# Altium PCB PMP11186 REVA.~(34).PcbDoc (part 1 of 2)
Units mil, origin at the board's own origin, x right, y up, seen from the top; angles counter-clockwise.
Board outline 5750 x 3370 mil, 4 copper layers (Top Layer, Signal Layer 1, Signal Layer 2, Bottom Layer), stack 85.4 mil thick; 92 components, 39 nets, 228 pads, 139 vias.
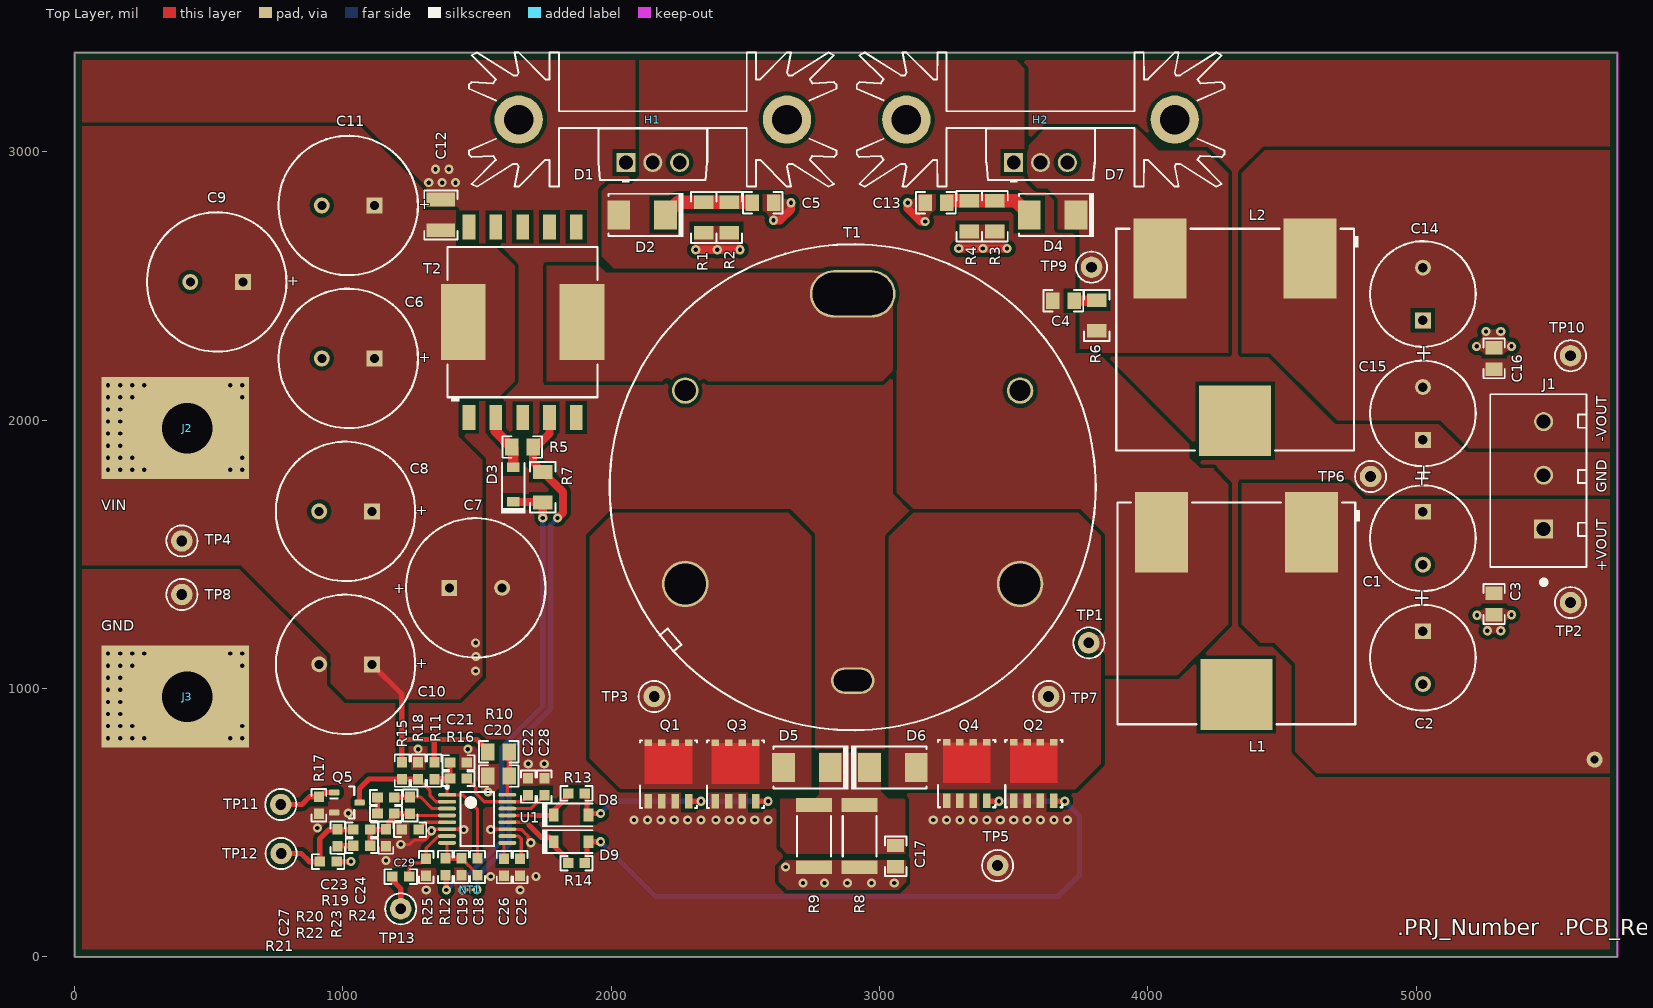
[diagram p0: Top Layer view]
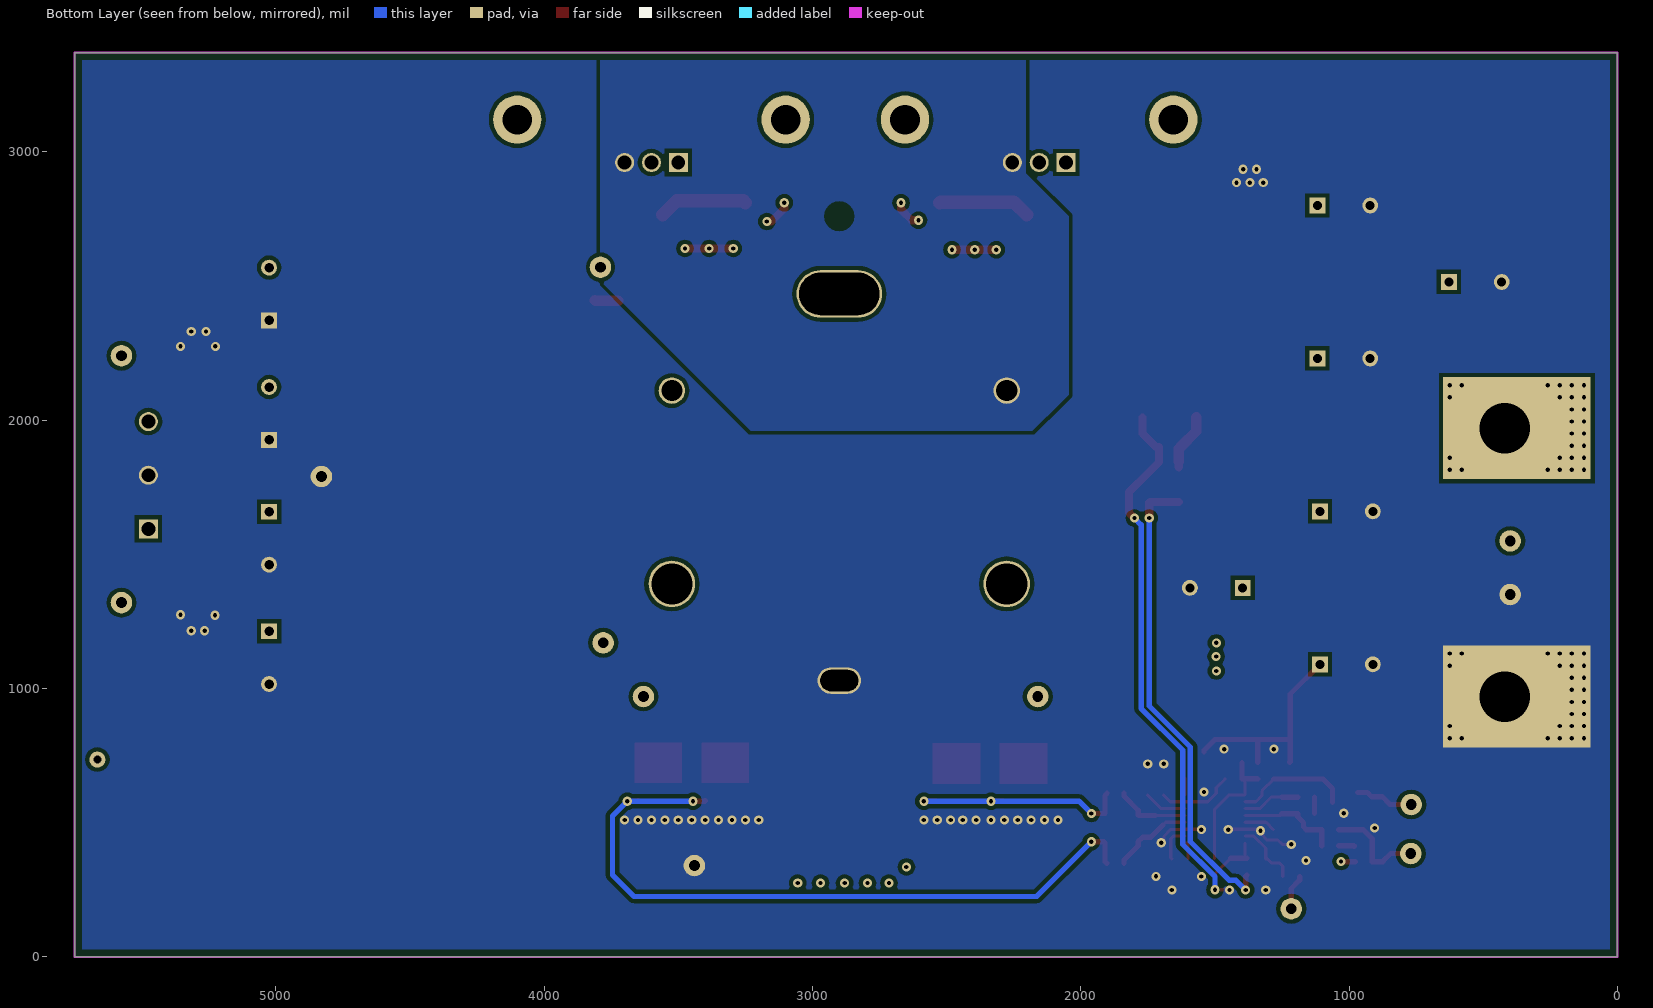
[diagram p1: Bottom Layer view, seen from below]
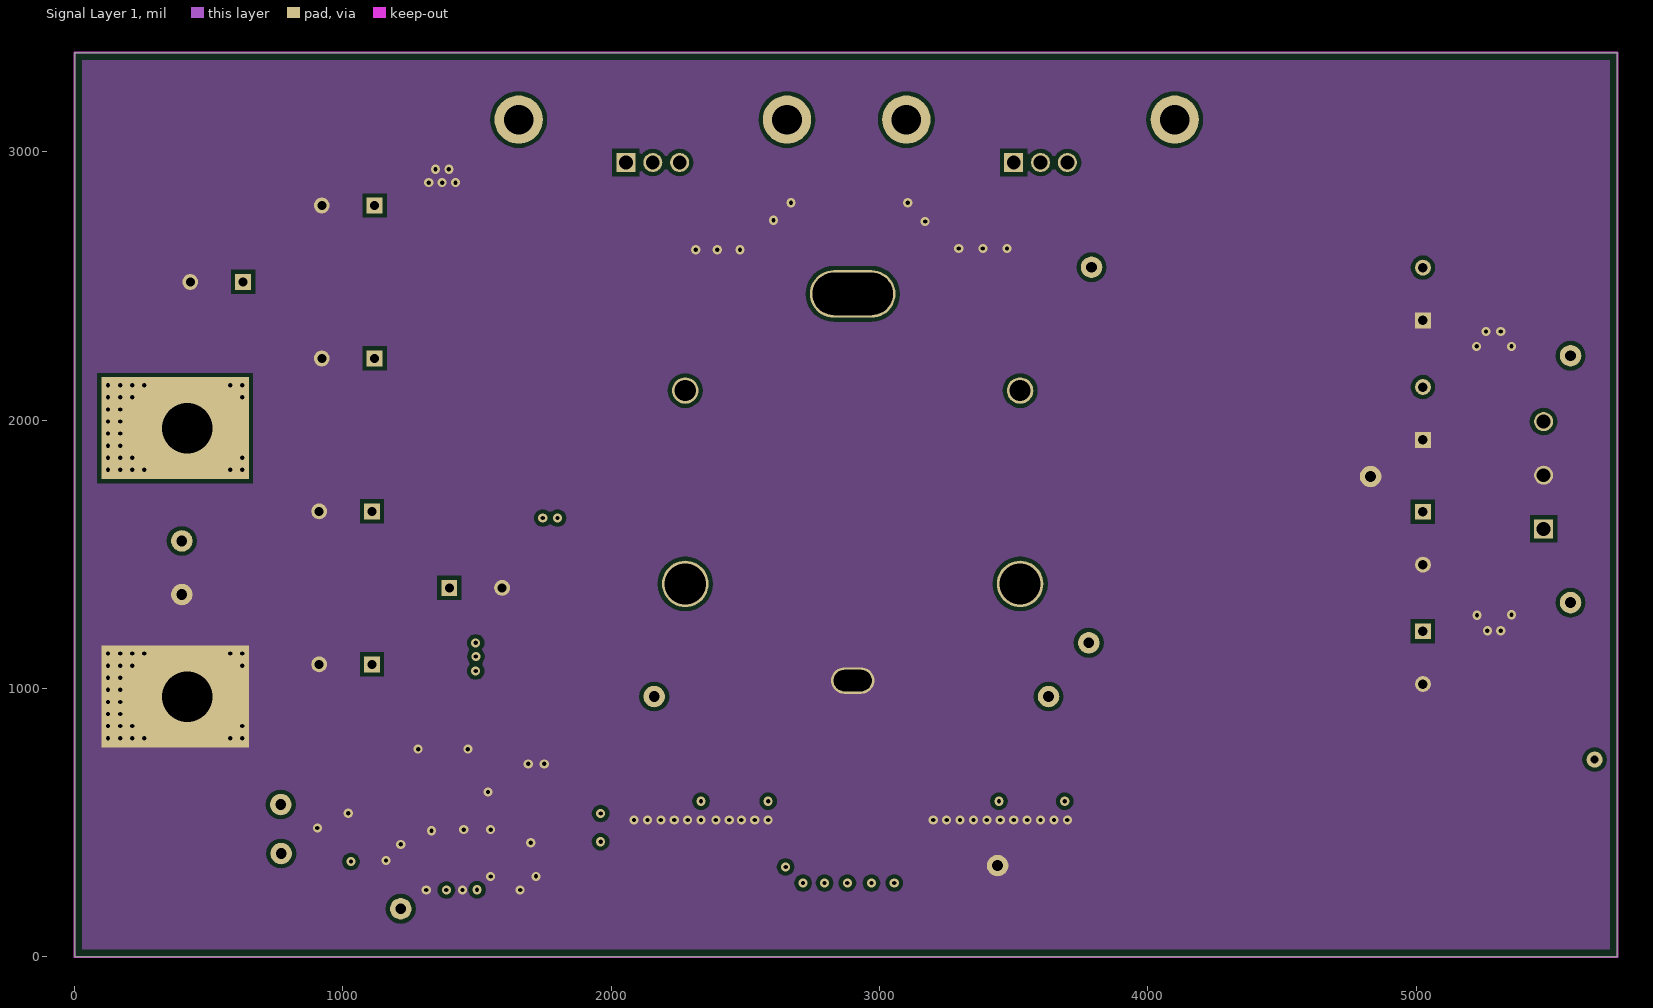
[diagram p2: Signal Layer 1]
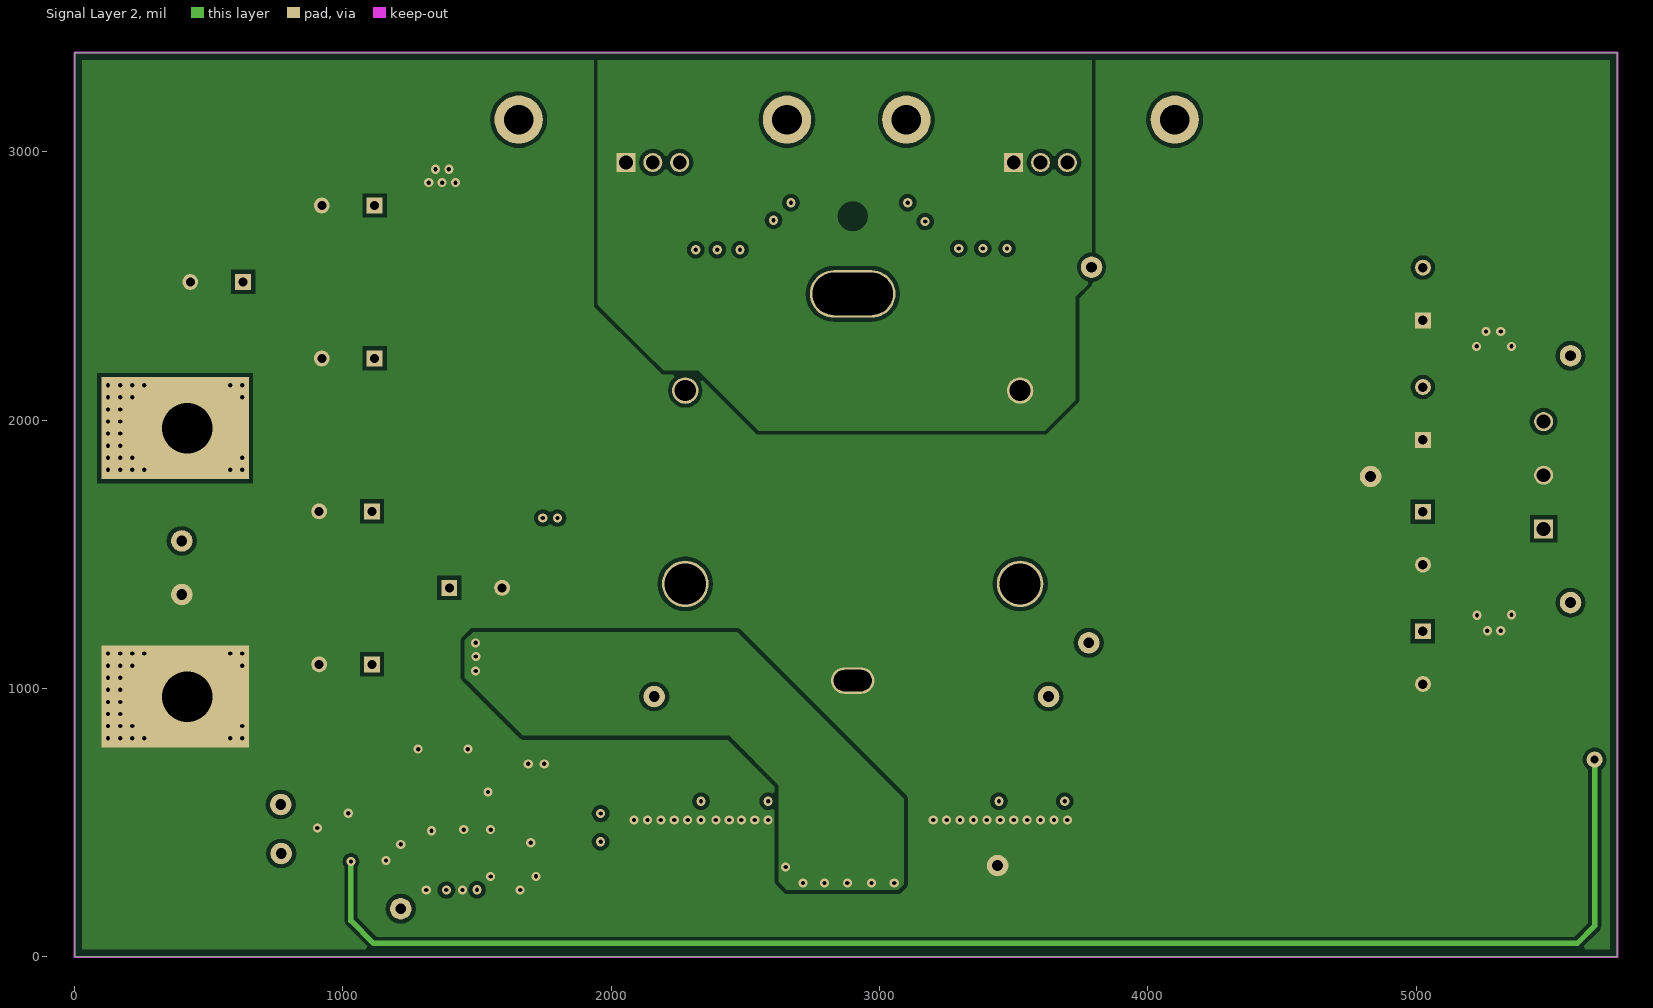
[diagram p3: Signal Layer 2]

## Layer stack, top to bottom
Top Solder: solder mask 0.4, Solder Resist, Dk 3.5
Top Layer: signal copper 2.8
Dielectric1: core 59.2, FR-4, Dk 4.8
Signal Layer 1: signal copper 2.8
Dielectric 3: prepreg 5, Dk 4.2
Signal Layer 2: signal copper 2.8
Dielectric 2: core 10, Dk 4.2
Bottom Layer: signal copper 2.8
Bottom Solder: solder mask 0.4, Solder Resist, Dk 3.5

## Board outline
0,0 5750,0 5750,3370 0,3370

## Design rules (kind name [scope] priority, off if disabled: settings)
AcuteAngle [All] p1: minimum=4.50000000000000E+0001 checktracksonly=FALSE
AssemblyTestPointUsage [All] p1: valid=2
Clearance Clearance_Keepouts [((IsTrack Or IsArc) And Not InPoly) And IsFree and IsKeepOut vs ((IsTrack Or IsArc) And Not InPoly) And IsFree and IsKeepOut] p1: gap=0
Clearance Clearance_BoardEdge_MountingHoles [OnCopper and InComponentClass('Mounting Holes') vs IsKeepOut] p2: gap=40
Clearance Clearance_BoardEdge_Poly [OnCopper and InPoly vs IsKeepOut] p3: gap=25
Clearance Clearance_BoardEdge [OnCopper and Not InComponentClass('Logo') and not InComponentClass('FiducialMark') and not InRegion(1000,500,4000,800) and Not IsKeepout vs IsKeepOut] p4: gap=25
Clearance Clearance_Poly [InPolygon] p5: gap=15
Clearance [All] p6: gap=7.87
ComponentClearance ComponentClearance_MountingHoles_FiducialMarks [InComponentClass('Mounting Holes') vs InComponentClass('FiducialMark')] p1: gap=50 collisioncheckmode=3 verticalgap=10 showdistances=FALSE
ComponentClearance ComponentClearance_Shunt [InComponentClass('Header') vs InComponentClass('Shunt')] p2: gap=0 collisioncheckmode=3 verticalgap=0 showdistances=FALSE
ComponentClearance ComponentClearance_Logo [InComponentClass('Logo')] p3: gap=50 collisioncheckmode=3 verticalgap=10 showdistances=FALSE
ComponentClearance ComponentClearance_ScrewToNut [(HasFootprint('NY PMS 440 0025 PH')) vs (HasFootprint('Keystone_1902C'))] p4: gap=5 collisioncheckmode=3 verticalgap=10 showdistances=FALSE
ComponentClearance ComponentClearance_MountingHoles [InComponentClass('Mounting Holes')] p5: gap=150 collisioncheckmode=3 verticalgap=100000 showdistances=FALSE
ComponentClearance ComponentClearance_SmallPassives [HasFootprint('0201*') or HasFootprint('0402*') or HasFootprint('0508') or HasFootprint('0603*') or HasFootprint('0612') or HasFootprint('0805*') or HasFootprint('0815*') or HasFootprint('0830*') or HasFootprint('1206*') or HasFootprint('1210*') or HasFootprint('1808*') or HasFootprint('1812*') or HasFootprint('1825*') or HasFootprint('2010*') or HasFootprint('2220*') or HasFootprint('2225*') or HasFootprint('2512*') or HasFootprint('2728*') or HasFootprint('3518*') vs HasFootprint('0201*') or HasFootprint('0402*') or HasFootprint('0508') or HasFootprint('0603*') or HasFootprint('0612') or HasFootprint('0805*') or HasFootprint('0815*') or HasFootprint('0830*') or HasFootprint('1206*') or HasFootprint('1210*') or HasFootprint('1808*') or HasFootprint('1812*') or HasFootprint('1825*') or HasFootprint('2010*') or HasFootprint('2220*') or HasFootprint('2225*') or HasFootprint('2512*') or HasFootprint('2728*') or HasFootprint('3518*')] p6: gap=15 collisioncheckmode=3 verticalgap=10 showdistances=FALSE
ComponentClearance ComponentClearance_THtoSMT [IsThruComponent vs IsSMTComponent] p7: gap=25 collisioncheckmode=3 verticalgap=30 showdistances=FALSE
ComponentClearance ComponentClearance_THtoTH [IsThruComponent vs IsThruComponent] p8: gap=25 collisioncheckmode=3 verticalgap=30 showdistances=FALSE
ComponentClearance [All] p9: gap=25 collisioncheckmode=3 verticalgap=10 showdistances=FALSE
DiffPairsRouting [All] p1: maxlimit=100 minlimit=10 mostfreqgap=10 toplayer_minwidth=15 toplayer_maxwidth=15 toplayer_prefwidth=15 midlayer1_minwidth=15 midlayer1_maxwidth=15 midlayer1_prefwidth=15 midlayer2_minwidth=15 midlayer2_maxwidth=15 midlayer2_prefwidth=15 bottomlayer_minwidth=15 bottomlayer_maxwidth=15 bottomlayer_prefwidth=15 maxuncoupledlength=1000
FabricationTestPointUsage TestPointUsage [All] p1: valid=2 allowmultiple=FALSE
FabricationTestpoint Testpoint [All] p1: side=3 testpointundercomponent=TRUE minsize=40 maxsize=100 preferedsize=60 minholesize=0 maxholesize=40 preferedholesize=32 testpointgrid=1 allowsidetop=TRUE allowsidebottom=TRUE usegrid=TRUE gridtolerance=0.01
FanoutControl Fanout_LCC [IsLCC] p1: bgadir=Out bgaviamode=Centered fanoutstyle=Auto fanoutdirection=Alternating viagrid=1 // Fanout_LCC (Default Rule)
FanoutControl Fanout_BGA [IsBGA] p2: bgadir=Out bgaviamode=Centered fanoutstyle=Auto fanoutdirection=Alternating viagrid=1 // Fanout_BGA (Default Rule)
FanoutControl Fanout_Default [All] p4: bgadir=Out bgaviamode=Centered fanoutstyle=Auto fanoutdirection=Alternating viagrid=1 // Fanout_Default (Default Rule)
FanoutControl Fanout_Small [(CompPinCount < 5)] p5: bgadir=Out bgaviamode=Centered fanoutstyle=Auto fanoutdirection=OutThenIn viagrid=1 // Fanout_Small (Default Rule)
HoleSize [All] p1: absolutevalues=TRUE maxlimit=251 minlimit=8 maxpercent=80.000 minpercent=20.000
MinimumAnnularRing MinimumAnnularRing_ThermalPadVias [IsVia and InAnyComponent] p1: minimumring=5.91
MinimumAnnularRing [All] p2: minimumring=9
MinimumSolderMaskSliver MinimumSolderMaskSliver_Logo [InComponentClass('Logo') vs InComponentClass('Logo')] p1: minsoldermaskwidth=0.7
MinimumSolderMaskSliver [All] p2: minsoldermaskwidth=3.94
PlaneClearance [All] p1: clearance=12
PlaneConnect [All] p1: planeconnectstyle=Direct reliefexpansion=10 reliefentries=4 reliefconductorwidth=10 reliefairgap=10
PolygonConnect [All] p1: connectstyle=Direct reliefconductorwidth=10 reliefentries=4 polygonreliefangle="90 Angle" airgapwidth=10
RoutingVias ThermalPadVias [IsVia and InAnyComponent] p1: holewidth=7.87 width=19.68 viastyle="Through Hole" minholewidth=7.87 minwidth=19.68 maxholewidth=12.99 maxwidth=23.62
RoutingVias [All] p2: holewidth=16 width=34 viastyle="Through Hole" minholewidth=7.87 minwidth=26 maxholewidth=40 maxwidth=65
SilkToBoardRegionClearance [Not ((IsComment or IsDesignator) And (Hide <> 'False')) and not InRegion(1000,500,4000,800)] p1:
SilkToSilkClearance SilkToSilkClearance_Pb-FreeLogo [(HasFootprint('Pb-Free_Overlay_Medium') OR HasFootprint('Pb-Free_Overlay_Small')) vs (HasFootprint('Pb-Free_Overlay_Medium') OR HasFootprint('Pb-Free_Overlay_Small'))] p1: silktosilkclearance=0
SilkToSilkClearance [All] p2: silktosilkclearance=0
SilkToSolderMaskClearance "Silk to Solder Mask Opening" [All] p1: minsilkscreentomaskgap=1 clearancetoexposedcopper=FALSE
SolderMaskExpansion [All] p1: expansion=1.97
UnpouredPolygon [All] p1: allowunpoured=FALSE
Width [All] p1: maxlimit=100 minlimit=6 preferedwidth=10 checkconnectedcopper=TRUE
13 further rules are at their usual default settings.

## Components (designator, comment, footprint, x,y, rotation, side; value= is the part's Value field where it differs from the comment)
C1 "35ZL470MEFC10X20" CAPPR5-10X20 5025,1560 r270 top
C2 "35ZL470MEFC10X20" CAPPR5-10X20 5025,1115 r270 top
C3 "GRM21BR71H105KA12L" 0805_HV 5290,1315 r270 top
C4 "GRM21A5C2E101JW01D" 0805_HV 3685,2445 r0 top
C5 "C2012X7R2A103M" 0805_HV 2565,2810 r0 top
C6 "25ZLH2700M12.5X35" ZLH_1250x2500 1020,2230 r180 top
C7 "25ZLH2700M12.5X35" ZLH_1250x2500 1495,1375 r0 top
C8 "25ZLH2700M12.5X35" ZLH_1250x2500 1010,1660 r180 top
C9 "25ZLH2700M12.5X35" ZLH_1250x2500 530,2515 r180 top
C10 "25ZLH2700M12.5X35" ZLH_1250x2500 1010,1090 r180 top
C11 "25ZLH2700M12.5X35" ZLH_1250x2500 1020,2800 r180 top
C12 "C3225X7R1E106M" 1210 1365,2765 r90 top
C13 "C2012X7R2A103M" 0805_HV 3210,2810 r0 top
C14 "35ZL470MEFC10X20" CAPPR5-10X20 5025,2470 r90 top
C15 "35ZL470MEFC10X20" CAPPR5-10X20 5025,2025 r90 top
C16 "GRM21BR71H105KA12L" 0805_HV 5290,2230 r270 top
C17 "C2012X7R2A103M" 0805_HV 3060,375 r90 top
C18 "C1608C0G1H152J" 0603 1501.98,335.31 r270 top
C19 "C1608C0G1H101J" 0603 1441.98,335.31 r90 top
C20 "C2012X7R1E105K" 0805_HV 1580.68,674.01 r180 top
C21 "" 0603 1430.68,724.01 r180 top
C22 "C1608X7R1C105K" 0603 1690.68,634.01 r270 top
C23 "C1608X7R1H473K" 0603 1160.68,594.01 r0 top
C24 "C1608C0G1H150J" 0603 1250.68,564.01 r270 top
C25 "C1608X7R1C105K" 0603 1660.68,334.01 r270 top
C26 "C1608X7R1H103K" 0603 1600.68,334.01 r270 top
C27 "" 0603 980.68,444.01 r90 top
C28 "C1608X7R1C105K" 0603 1750.68,634.01 r90 top
C29 "C1608C0G1H101J" 0603 1215.68,299.01 r0 top
D1 "FML22S" ITO-220AB 2155,2960 r0 top
D2 "MURS120-13-F" SMB 2115,2765 r180 top
D3 "MMSD4148T1G" SOD-123 1635,1760 r90 top
D4 "MURS120-13-F" SMB 3645,2765 r180 top
D5 "MURS120-13-F" SMB 2729.45,705.28 r180 top
D6 "MURS120-13-F" SMB 3049.45,705.28 r0 top
D7 "FML22R" ITO-220AB 3600,2960 r0 top
D8 "BAT54T1G" SOD-123 1850.68,529.01 r0 top
D9 "BAT54T1G" SOD-123 1850.68,429.01 r0 top
H1 "513201B02500G" HSINK_513201B02500 2155,3120 r0 top
H2 "513201B02500G" HSINK_513201B02500 3600,3120 r0 top
J1 "OSTTA034163" On-Shore_OSTTA034163 5455,1775 r90 top
J2 "CB35-36-CY" CB35-36-CY 420,1970 r0 top
J3 "CB35-36-CY" CB35-36-CY 420,970 r0 top
L1 "B82559A0353A020" B82559_1420 4330,1280 r270 top
L2 "B82559A0353A020" B82559_1420 4325,2300 r270 top
NT1 "Net-Tie" Net-Tie_10mil 1475,250 r180 top net-tie
Q1 "DNP" TRANS_NexFET_Q5B 2213.12,688.44 r90 top
Q2 "DNP" TRANS_NexFET_Q5B 3574.72,690.58 r90 top
Q3 "CSD18540Q5B" TRANS_NexFET_Q5B 2463.12,688.44 r90 top
Q4 "CSD18540Q5B" TRANS_NexFET_Q5B 3324.72,690.58 r90 top
Q5 "2N7002P,215" SOT-23 1015,575 r0 top
R1 "" 1206 2345,2755 r90 top
R2 "CRCW120649K9FKEA" 1206 2440,2755 r90 top
R3 "" 1206 3430,2760 r270 top
R4 "CRCW120649K9FKEA" 1206 3335,2760 r270 top
R5 "CRCW08051K00FKEA" 0805_HV 1668.74,1900 r0 top
R6 "CRCW1206100RFKEA" 1206 3810,2390 r90 top
R7 "CSR1206FKR750" 1206 1745,1750 r270 top
R8 "" 2512 2925.68,449.81 r270 top
R9 "CRCW251210K0JNEG" 2512 2755.68,449.81 r270 top
R10 "ERJ-6GEYJ4R7V" 0805_HV 1580.68,764.01 r180 top
R11 "" 0603 1340.68,694.01 r270 top
R12 "CRCW06031K00FKEA" 0603 1381.98,335.31 r270 top
R13 "CRCW06031R00FKEA" 0603 1870.68,609.01 r0 top
R14 "CRCW06031R00FKEA" 0603 1870.68,349.01 r0 top
R15 "CRCW0603130KFKEA" 0603 1220.68,694.01 r90 top
R16 "CRCW0603200KFKEA" 0603 1430.68,664.01 r180 top
R17 "CRCW060310K0FKEA" 0603 910.89,565 r90 top
R18 "CRCW060321K0FKEA" 0603 1280.68,694.01 r270 top
R19 "CRCW0603100KFKEA" 0603 1160.68,534.01 r180 top
R20 "CRCW060347K5FKEA" 0603 1070.68,474.01 r180 top
R21 "CRCW060349R9FKEA" 0603 945,355 r180 top
R22 "" 0603 1070.68,414.01 r180 top
R23 "CRCW06032K49FKEA" 0603 1160.68,444.01 r90 top
R24 "CRCW060349K9FKEA" 0603 1250.68,474.01 r0 top
R25 "CRCW060329K4FKEA" 0603 1310.68,334.01 r90 top
T1 "G154027ALF" GCI_G154027ALF 2900,1750 r90 top
T2 "G154028ALF" GCI_G154028ALF 1670,2365 r90 top
TP1 "5000" Keystone5000 3780,1170 r0 top
TP2 "5000" Keystone5000 5575,1320 r0 top
TP3 "5000" Keystone5000 2160,970 r0 top
TP4 "5000" Keystone5000 400,1550 r0 top
TP5 "5001" Keystone5001 3440,340 r0 top
TP6 "5001" Keystone5001 4830,1790 r0 top
TP7 "5000" Keystone5000 3630,970 r0 top
TP8 "5001" Keystone5001 400,1350 r0 top
TP9 "5000" Keystone5000 3790,2570 r0 top
TP10 "5000" Keystone5000 5575,2240 r0 top
TP11 "5000" Keystone5000 768.65,567.6 r0 top
TP12 "5000" Keystone5000 770,385 r0 top
TP13 "5000" Keystone5000 1215.68,179.01 r0 top
U1 "LM25037QMT" MTC16_N 1500.68,514.01 r0 top

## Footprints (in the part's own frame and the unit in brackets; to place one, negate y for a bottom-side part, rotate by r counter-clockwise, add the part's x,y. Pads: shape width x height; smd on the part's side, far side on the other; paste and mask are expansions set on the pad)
0603 [mm] "0603 from SM-752 data"
  rect 1x0.95 smd: 1(-0.8,0) 2(0.8,0)
  silkscreen extent -1.52,-0.69 1.52,0.69, body extent -0.87,-0.47 0.87,0.47, height 0.85
0805_HV [mil] "0805 with 30mil clearance between pads"
  rect 50x63 smd: 1(-40,0) 2(40,0)
  silkscreen extent -74,-40 74,40, body extent -43,-29 43,29, height 57
1206 [mm] "1206 from SM-752 data"
  rect 1.3x1.85 smd: 1(-1.45,0) 2(1.45,0)
  silkscreen extent -2.4,-1.21 2.4,1.21, body extent -1.7,-0.9 1.7,0.9, height 1.35
1210 [mm] "1210 from SM-752 data"
  rect 1.3x2.7 smd: 1(-1.45,0) 2(1.45,0)
  silkscreen extent -2.32,-1.57 2.32,1.57, body extent -1.7,-1.35 1.7,1.35, height 1.35
2512 [mm] "Chip Resistor, Body 6.3x3.2mm, IPC Medium Density"
  rect 1.3x3.4 smd: 1(-2.95,0) 2(2.95,0)
  silkscreen extent -1.9,-1.6 1.9,1.6, body extent -3.22,-1.67 3.22,1.67, height 0.71
B82559_1420 [mm] "SMD, 3-Leads, Body 21.5x21mm"
  rect 7.6x5 smd: 1(-7.675,7.1) 2(-7.675,-7.1)
  rect 6.7x6.8 smd: 3(7.675,0)
  silkscreen extent -10.5,-11.25 10.5,11.7, body extent -11,-11.25 11,11.25, height 14.2
CAPPR5-10X20 [mm] "Capacitor, Electrolytic, Radial; Body 10 x 20 mm (Dia.xH typ); Pin Spacing 5 mm (typ)"
  rect 1.5x1.5 hole 0.9: 1(-2.5,0)
  round 1.5 hole 0.9: 2(2.5,0)
  silkscreen extent -5,-5 5,5, body extent -5.01,-5.01 5.01,5.01, height 22
CB35-36-CY [mil] "Terminal 50A Lug"
  rect 550x380 hole 188 copper offset -45,0 paste-190: 1(0,0)
  body extent -960,-189 230,191, height 614
GCI_G154027ALF [mm] "TH, 6-Leads, Dia 46mm"
  round 4.4 hole 3.9: 1(-9.15,15.848) 3(-9.15,-15.848)
  oval 2.5x4.1 hole 2 slot 3.6 at 90 deg: 2(-18.3,0)
  round 2.5 hole 2: 4(9.15,-15.848) 6(9.15,15.848)
  oval 4.5x8.1 hole 4 slot 7.6 at 90 deg: 5(18.3,0)
  silkscreen extent -23,-23 23,23, body extent -23.01,-23.01 23.01,23.01, height 28
GCI_G154028ALF [mm] "SMD, 12-Leads, Body 14.2x20mm, Pitch 2.54mm"
  rect 2.35x1.2 smd: 1(-9.025,5.08) 2(-9.025,2.54) 3(-9.025,0) 4(-9.025,-2.54) 5(-9.025,-5.08) 6(9.025,-5.08) 7(9.025,-2.54) 8(9.025,0) 9(9.025,2.54) 10(9.025,5.08)
  rect 7.2x4.25 smd: 11(0,5.625) 12(0,-5.625)
  silkscreen extent -7.5,-7.1 7.1,7.1, body extent -10,-7.25 10,7.25, height 10.52
HSINK_513201B02500 [mil] "Aavid"
  round 180 hole 110.24: 1(-500,0) 2(500,0)
  silkscreen extent -685,-250 685,250, body extent -685,-250 685,250, height 2000
ITO-220AB [mm] "TH, 3-Leads, Body 10.11x15.87mm, Pitch 2.54mm"
  rect 1.8x1.8 hole 1.3: 1(-2.54,0)
  round 1.8 hole 1.3: 2(0,0) 3(2.54,0)
  silkscreen extent -5.16,-1.9 5.15,3.24, body extent -5.16,-1.66 5.16,3.24, height 19.67
Keystone5000 [mil] "For Keystone 500x miniature loop terminals"
  round 80 hole 40: 1(0,0)
  silkscreen extent -58,-58 58,58, body extent -49,-49 49,49, height 182
Keystone5001 [mil] "For Keystone 500x miniature loop terminals"
  round 80 hole 40: 1(0,0)
  silkscreen extent -58,-58 58,58, body extent -49,-49 49,49, height 182
MTC16_N [mm] "TSOP, 16-Leads, Body 5x4.4mm, Pitch 0.65mm, IPC Medium Density"
  oval 1.7x0.35 smd: 1(-2.85,2.275) 2(-2.85,1.625) 3(-2.85,0.975) 4(-2.85,0.325) 5(-2.85,-0.325) 6(-2.85,-0.975) 7(-2.85,-1.625) 8(-2.85,-2.275) 9(2.85,-2.275) 10(2.85,-1.625) 11(2.85,-0.975) 12(2.85,-0.325) 13(2.85,0.325) 14(2.85,0.975) 15(2.85,1.625) 16(2.85,2.275)
  silkscreen extent -2.97,-2.55 1.6,3.12, body extent -2.25,-2.55 2.25,2.55, height 1.1
Net-Tie_10mil [mil] "10mil net tie, no solder mask opening, no solder paste"
  rect 10x10 smd paste-5 mask-5: 1(-10,0) 2(10,0)
  Top Layer region: -6,5 6,5 6,-5 -6,-5
On-Shore_OSTTA034163 [mm] "TERM BLOCK 3x1, 5.08mm, TH"
  rect 1.8x1.8 hole 1.3: 1(-4.58,-0.5)
  round 1.8 hole 1.3 paste+0: 2(0.5,-0.5) 3(5.58,-0.5)
  silkscreen extent -9.73,-4.55 8.17,4.55, body extent -8.22,-4.6 8.22,4.6, height 13
SMB [mil] "Molded Diode, 2-Leads, Body 5.4x3.6mm, IPC Medium Density, based on OnSemi component dimensions"
  rect 85x107.99 smd: 1(-87.01,0) 2(87.01,0)
  silkscreen extent -155,-82 125,82, body extent -106,-71 106,71, height 91
SOD-123 [mm] "On Semi recommended land pattern"
  rect 0.915x1.22 smd: 1(-1.637,0) 2(1.637,0)
  silkscreen extent -2.74,-1.17 2.03,1.17, body extent -1.93,-0.9 1.93,0.9, height 1.35
SOT-23 [mm] "SOT23, 3-Leads, Body 2.9x1.3mm, Pitch 0.95mm, Lead Span 2.5mm, IPC Medium Density"
  rrect50% 1x0.6 smd: 1(-1.2,0.95) 2(-1.2,-0.95) 3(1.2,0)
  silkscreen extent -1.63,-1.5 0.7,1.5, body extent -1.16,-1.45 1.21,1.45, height 1
TRANS_NexFET_Q5B [mm] "TI recommended land pattern (nominal) November 2012"
  rect 1.372x0.71 smd paste-0.4: 1(-2.776,1.905) 2(-2.776,0.635) 3(-2.776,-0.635) 4(-2.776,-1.905)
  rect 0.59x0.71 smd paste-0.3: 5(2.776,-1.905) 6(2.776,-0.635) 7(2.776,0.635) 8(2.776,1.905)
  Top Layer region: -1.106,-2.26 2.744,-2.26 2.744,2.26 -1.106,2.26
  silkscreen extent -3.38,-2.7 3,2.7, body extent -3.23,-2.55 2.87,2.55, height 1.06
ZLH_1250x2500 [mm] "Rubycon"
  rect 1.5x1.5 hole 0.85: 1(-2.5,0)
  round 1.5 hole 0.85: 2(2.5,0)
  silkscreen extent -6.6,-6.6 6.6,6.6, body extent -6.45,-6.49 6.49,6.49, height 26.51

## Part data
C1 C2 C14 C15: "CAP, AL, 470 µF, 35 V, 0.023 Ohms, 1.82A, TH"
C3 C16: "CAP, CERM, 1uF, 50V, +/-10%, X7R, 0805"
C4: "CAP, CERM, 100 pF, 250 V, +/- 5%, C0G/NP0, 0805"
C5 C13 C17: "CAP, CERM, 0.01 µF, 100 V, +/- 20%, X7R, 0805"
C6 C7 C8 C9 C10 C11: library part 63ZLH470M12.5X25, "CAP, AL, 2700 µF, 25 V, 0.016 ohm, 4.12A, TH"
C12: "CAP, CERM, 10 µF, 25 V, +/- 20%, X7R, 1210"
C18: "CAP, CERM, 1500 pF, 50 V, +/- 5%, C0G/NP0, 0603"
C19 C29: "CAP, CERM, 100 pF, 50 V, +/- 5%, C0G/NP0, 0603"
C20: "CAP, CERM, 1 µF, 25 V, +/- 10%, X7R, 0805"
C21 C27: library part C1608C0G1H271J, "CAP, DNP, 0603"
C22 C25 C28: "CAP, CERM, 1 µF, 16 V, +/- 10%, X7R, 0603"
C23: "CAP, CERM, 0.047 µF, 50 V, +/- 10%, X7R, 0603"
C24: "CAP, CERM, 15 pF, 50 V, +/- 5%, C0G/NP0, 0603"
C26: "CAP, CERM, 0.01 µF, 50 V, +/- 10%, X7R, 0603"
D1 D7: "Diode, Ultrafast, 200 V, 10 A, TH"
D2 D4 D5 D6: "Diode, Superfast Rectifier, 200 V, 1 A, SMB"
D3: "Diode, Switching, 100 V, 0.2 A, SOD-123"
D8 D9: "Diode, Schottky, 30V, 0.2A, SOD-123"
H1 H2: "HEATSINK TO-218/TO-247 W/PINS 2\""
J1: "Terminal Block, 3x1, 5.08 mm, TH"
J2 J3: "Terminal 50A Lug"
L1 L2: "Inductor, Wirewound, Ferrite, 35 µH, 9.3 A, 0.007 ohm, SMD"
NT1: "Single point connection between nets."
Q1 Q2: library part CSD18540Q5B, "MOSFET, DNP, SON 5x6mm"
Q3 Q4: "MOSFET, N-CH, 60 V, 28 A, SON 5x6mm"
Q5: "MOSFET, N-CH, 60 V, 0.36 A, SOT-23"
R1 R3: library part CRCW120649K9FKEA, "RES, DNP, 1206"
R2 R4: "RES, 49.9 k, 1%, 0.25 W, 1206"
R5: "RES, 1.00 k, 1%, 0.125 W, 0805"
R6: "RES, 100 ohm, 1%, 0.25W, 1206"
R7: "RES, 0.75, 1%, 0.5 W, 1206"
R8: library part CRCW251210K0JNEG, "RES, DNP, 2512"
R9: "RES, 10 k, 5%, 1 W, 2512"
R10: "RES, 4.7, 5%, 0.125 W, 0805"
R11 R22: library part CRCW060332K4FKEA, "RES, DNP, 0603"
R12: "RES, 1.00 k, 1%, 0.1 W, 0603"
R13 R14: "RES, 1.00 ohm, 1%, 0.1W, 0603"
R15: "RES, 130 k, 1%, 0.1 W, 0603"
R16: "RES, 200 k, 1%, 0.1 W, 0603"
R17: "RES, 10.0k ohm, 1%, 0.1W, 0603"
R18: "RES, 21.0 k, 1%, 0.1 W, 0603"
R19: "RES, 100 k, 1%, 0.1 W, 0603"
R20: "RES, 47.5 k, 1%, 0.1 W, 0603"
R21: "RES, 49.9, 1%, 0.1 W, 0603"
R23: "RES, 2.49k ohm, 1%, 0.1W, 0603"
R24: "RES, 49.9 k, 1%, 0.1 W, 0603"
R25: "RES, 29.4 k, 1%, 0.1 W, 0603"
T1: "Transformer, 50 uH, TH"
T2: "Transformer, 22.4 mH, SMT"
TP1 TP2 TP3 TP4 TP7 TP9 TP10 TP11 TP12 TP13: "Test Point, Miniature, Red, TH"
TP5 TP6 TP8: "Test Point, Miniature, Black, TH"
U1: "Dual-Mode PWM Controller With Alternating Outputs, Automotive Grade, 16-pin TSSOP"

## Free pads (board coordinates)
  round 60 hole 30: 0(5665,735)

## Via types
v1: diameter 34, hole 16, Top Layer to Bottom Layer, 83 vias
v2: diameter 32, hole 16, Top Layer to Bottom Layer, 56 vias

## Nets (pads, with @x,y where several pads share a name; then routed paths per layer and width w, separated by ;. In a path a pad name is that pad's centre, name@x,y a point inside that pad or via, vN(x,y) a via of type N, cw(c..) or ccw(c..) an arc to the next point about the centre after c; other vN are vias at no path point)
GND: C1.2 C2.2 C3.2 C5.2 C6.2 C7.2 C8.2 C9.2 C10.2 C11.2 C12.2 C13.1 C14.1 C15.1 C16.1 C19.1 C20.2 C21.1 C22.1 C25.2 C26.2 C28.2 J1.2 J3.1 NT1.2 Q1.1 Q1.2 Q1.3 Q2.1 Q2.2 Q2.3 Q3.1 Q3.2 Q3.3 Q4.1 Q4.2 Q4.3 Q5.2 R1.1 R2.1 R3.2 R4.2 R17.1 R18.1 R23.1 R24.1 R25.1 T1.2 TP5.1 TP6.1 TP8.1 U1.6 U1.11 | length 1022.5
  Top Layer w12: v1(1215.68,419.01) 1249.01,419.01 1265,435 1305,435 1330,460 v1(1330,470) 1335.63,475.63 U1.6@1388.48,475.63 1449.07,475.63 v1(1450.68,474.01) ; v1(1445.68,249.01) 1446.67,250 NT1.2@1465,250 ; v1(1550.68,474.01) 1552.3,475.63 U1.11@1612.89,475.63 1613.52,475 1665,475 1690,450 1690,435 v1(1700,425)
  Top Layer w30: v1(2315,2635) v1(2480,2635) ; v1(2605,2745) 2630,2745 2670,2785 v1(2670,2810) ; v1(3105,2810) 3105,2788.6 3153.6,2740 v1(3170,2740) ; v1(3295,2640) v1(3385,2640) v1(3475,2640)
  other v1: 1310.68,249.01 1660.68,249.01 1550.68,299.01 1720,300 1160.68,359.01 905,480 2085,510 2135,510 2185,510 2235,510 2285,510 2335,510 2390,510 2440,510 2485,510 2535,510 2585,510 3200,510 3250,510 3300,510 3350,510 3400,510 3450,510 3500,510 3550,510 3600,510 3650,510 3700,510 1020,535 1540.68,614.01 1690.68,719.01 1750.68,719.01 1280.68,774.01 1465.68,774.01 5265,1215 5315,1215 5226.59,1272.95 5355,1275 5225,2275 5355,2275 5260,2330 5315,2330 2395,2635 1320,2885 1370,2885 1420,2885 1345,2935 1395,2935
  other v2: 125,815 170,815 215,815 260,815 580,815 625,815 125,860 170,860 215,860 625,860 125,905 170,905 125,950 170,950 125,995 170,995 125,1040 170,1040 125,1085 170,1085 215,1085 625,1085 125,1130 170,1130 215,1130 260,1130 580,1130 625,1130
NetC4_1: C4.1 D1.2 D2.2 L1.2 TP1.1
NetC4_2: C4.2 R6.2 | length 85.9
  Top Layer w40: C4.2@3725,2445 3807.91,2445 R6.2@3810,2447.09
NetC5_1: C5.1 D2.1 R1.2 R2.2 | length 343.4
  Top Layer w50: D2.1@2202.01,2765 2249.09,2812.09 R1.2@2345,2812.09 R2.2@2440,2812.09 2522.91,2812.09 C5.1@2525,2810
NetC6_1: C6.1 C7.1 C8.1 C9.1 C10.1 C11.1 C12.1 C17.1 J2.1 R8.2 R9.2 R10.2 R11.1 R15.2 T2.11 TP4.1 | length 838.6
  Top Layer w20: C10.1@1108.43,1090 1220,978.43 1220,810 ; R15.2@1220.68,725.51 1220,726.19 1220,810 ; R11.1@1340.68,725.51 1340.68,809.32 1340,810 ; R10.2@1540.68,764.01 1540.68,769.32 1500,810 1340,810 ; 1220,810 1340,810
  other v1: 2715,275 2795,275 2880,275 2970,275 3055,275 2650,335 1495,1065 1495.72,1119.52 1495,1170
  other v2: 125,1815 170,1815 215,1815 260,1815 580,1815 625,1815 125,1860 170,1860 215,1860 625,1860 125,1905 170,1905 125,1950 170,1950 125,1995 170,1995 125,2040 170,2040 125,2085 170,2085 215,2085 625,2085 125,2130 170,2130 215,2130 260,2130 580,2130 625,2130
NetC13_2: C13.2 D4.2 R3.1 R4.1 | length 332.5
  Top Layer w50: C13.2@3250,2810 3257.09,2817.09 R4.1@3335,2817.09 R3.1@3430,2817.09 3505.91,2817.09 D4.2@3557.99,2765
NetC14_2: C14.2 C15.2 C16.2 J1.3 L2.1 TP10.1
NetC17_2: C17.2 D5.1 D6.1 R8.1 R9.1
NetC18_1: C18.1 C21.2 R11.2 R16.2 U1.1 | length 501.7
  Top Layer w12: R16.2@1399.19,664.01 1388.48,653.3 U1.1@1388.48,603.58 1446.42,603.58 1501.98,548.02 C18.1@1501.98,366.81
  Top Layer w20: R11.2@1340.68,662.52 1342.18,664.01 R16.2@1399.19,664.01 C21.2@1399.19,724.01
NetC18_2: C18.2 C19.2 R12.1 U1.8 | length 208.2
  Top Layer w12: R12.1@1381.98,366.81 1388.48,373.3 U1.8@1388.48,424.45 ; C19.2@1441.98,366.81 1501.98,306.81 C18.2@1501.98,303.82
  Top Layer w20: R12.1@1381.98,366.81 C19.2@1441.98,366.81
NetC20_1: C20.1 R10.1 U1.16 | length 152.6
  Top Layer w12: U1.16@1612.89,603.58 C20.1@1612.89,666.22
  Top Layer w20: C20.1@1620.68,674.01 R10.1@1620.68,764.01
NetC22_2: C22.2 R16.1 U1.15 | length 286.7
  Top Layer w12: R16.1@1462.18,664.01 1462.18,662.82 1495,630 1495,610 1527.01,577.99 U1.15@1612.89,577.99 1666.16,577.99 C22.2@1690.68,602.52
NetC23_1: C23.1 R19.2 | length 60
  Top Layer w20: R19.2@1129.19,534.01 C23.1@1129.19,594.01
NetC23_2: C23.2 C24.1 U1.3 | length 214.8
  Top Layer w12: C24.1@1250.68,595.51 1289.49,595.51 1332.6,552.4 U1.3@1388.48,552.4
  Top Layer w20: C23.2@1192.18,594.01 1249.19,594.01 C24.1@1250.68,595.51
NetC24_2: C24.2 R19.1 R20.1 R22.1 R23.2 U1.4 | length 390
  Top Layer w12: C24.2@1250.68,532.52 1256.39,526.81 U1.4@1388.48,526.81
  Top Layer w20: R22.1@1102.18,414.01 R20.1@1102.18,474.01 1159.19,474.01 R23.2@1160.68,475.51 1170,484.83 1170,500.47 1192.18,522.65 R19.1@1192.18,534.01 1193.68,532.52 C24.2@1250.68,532.52
NetC25_1: C25.1 U1.10 | length 132.5
  Top Layer w12: U1.10@1612.89,450.04 1654.96,450.04 1665,440 1665,369.83 C25.1@1660.68,365.51
NetC26_1: C26.1 U1.9 | length 68.3
  Top Layer w12: C26.1@1600.68,365.51 1600.68,419.58 1605.55,424.45 U1.9@1612.89,424.45
NetC27_1: C27.1 R22.2 | length 59.1
  Top Layer w20: C27.1@980.68,412.52 982.18,414.01 R22.2@1039.19,414.01
NetC27_2: C27.2 R20.2 R21.2 TP12.1 | length 380.2
  Top Layer w20: TP12.1@770,385 845,385 875,355 R21.2@913.5,355 913.5,439.18 948.33,474.01 R20.2@1039.19,474.01
NetC28_1: C28.1 U1.14 | length 158.6
  Top Layer w12: U1.14@1612.89,552.4 1700.57,552.4 C28.1@1750.68,602.52
NetC29_1: C29.1 TP13.1 | length 133
  Top Layer w20: C29.1@1184.19,299.01 1184.19,285.81 1215.68,254.32 TP13.1@1215.68,179.01
NetC29_2: C29.2 R25.2 U1.7 | length 249.7
  Top Layer w12: C29.2@1247.18,299.01 1247.18,337.18 1260,350 1290,350 1305.51,365.51 R25.2@1310.68,365.51 1310.68,405.68 1355.04,450.04 U1.7@1388.48,450.04
NetD1_1: D1.1 D7.1 T1.4
NetD1_3: D1.3 D7.3 T1.6
NetD3_1: D3.1 R7.2 R12.2 | length 1774.8
  Top Layer w20: R12.2@1381.98,303.82 1385.68,300.12 v1(1385.68,249.01)
  Top Layer w30: D3.1@1635,1695.53 1742.39,1695.53 R7.2@1745,1692.91 v1(1745,1635)
  Bottom Layer w20: v1(1385.68,249.01) 1421.67,285 1446.68,285 1592.13,430.45 1592.13,782.13 1745,935 v1(1745,1635)
NetD3_2: D3.2 R5.1 T2.2 | length 212.1
  Top Layer w30: D3.2@1635,1824.47 1635,1845
  Top Layer w40: T2.2@1570,2009.68 1570,1958.74 R5.1@1628.74,1900 1635,1893.74 1635,1845
NetD4_1: D4.1 D7.2 L2.2 R6.1 TP9.1
NetD5_2: D5.2 Q1.5 Q1.6 Q1.7 Q1.8 Q3.5 Q3.6 Q3.7 Q3.8 T1.1 TP3.1
NetD6_2: D6.2 Q2.5 Q2.6 Q2.7 Q2.8 Q4.5 Q4.6 Q4.7 Q4.8 T1.3 TP7.1
NetD8_1: D8.1 R13.1 U1.13 | length 276.2
  Top Layer w12: U1.13@1612.89,526.81 1723.19,526.81
  Top Layer w20: 1723.19,526.81 1784.01,526.81 D8.1@1786.22,529.01 1786.22,546.22 1839.19,599.19 R13.1@1839.19,609.01
NetD8_2: D8.2 Q1.4 Q3.4 R13.2 | length 866.7
  Top Layer w20: R13.2@1902.18,609.01 1910,601.19 1910,534.17 1910.15,534.01 v1(1960.68,534.01) ; Q1.4@2288.12,579.14 2288.98,580 v1(2335,580) ; Q3.4@2538.12,579.14 2538.98,580 v1(2585,580)
  Bottom Layer w20: v1(1960.68,534.01) 2006.67,580 v1(2335,580) v1(2585,580)
NetD9_1: D9.1 R14.1 U1.12 | length 305.2
  Top Layer w12: U1.12@1612.89,501.22 1683.78,501.22 1695,490
  Top Layer w20: 1695,490 1740,445 1770.23,445 D9.1@1786.22,429.01 1786.22,413.78 1839.19,360.81 R14.1@1839.19,349.01
NetD9_2: D9.2 Q2.4 Q4.4 R14.2 | length 2663.3
  Top Layer w20: R14.2@1902.18,349.01 1904.01,349.01 1910,355 1910,423.86 D9.2@1915.15,429.01 v1(1960.68,429.01) ; Q4.4@3399.72,581.28 3401,580 v1(3445,580) ; Q2.4@3649.72,581.28 3651,580 v1(3690,580)
  Bottom Layer w20: v1(1960.68,429.01) 2164.7,225 3665,225 3745,305 3745,525 v1(3690,580) v1(3445,580)
NetNT1_1: NT1.1 R5.2 R7.1 T2.4 | length 1970.3
  Top Layer w30: T2.4@1770,2009.68 1770,1950 1720,1900 R5.2@1708.74,1900 1708.74,1843.34 R7.1@1745,1807.08 1820,1732.09 1820,1655 v1(1800,1635)
  Bottom Layer w20: v1(1500,250) 1500,298.9 1620,418.9 1620,770.58 1775,925.58 1775,1610 v1(1800,1635)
